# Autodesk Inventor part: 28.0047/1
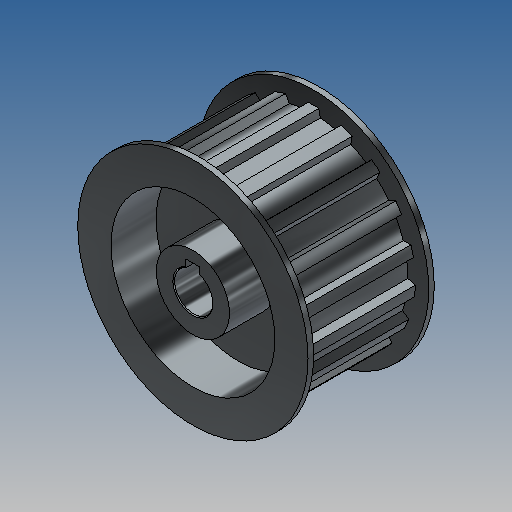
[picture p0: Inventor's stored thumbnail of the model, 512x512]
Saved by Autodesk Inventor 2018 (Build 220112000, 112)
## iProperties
Created: 2006-12
Document SubType Name: Modeling
Designer: Andy Moles
Material: Aluminum-6061
Part Number: 28.0047/1
Density: 2.71 g/cm^3
Description: T45 PULLEY 11mm
Appearance: Zinc
Author: Andy Moles
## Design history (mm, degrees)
sketch "Sketch1"
  geometry: L1 (-1.927, 26.982)-(-1.524, 29.17); L2 (1.927, 26.982)-(1.524, 29.17); L3 (11.073, 27.03)-(10.707, 24.842); L4 (15.084, 22.455)-(16.683, 23.977); L5 (19.077, 22.12)-(18.136, 20.071); L6 (21.534, 16.371)-(23.587, 17.23); L7 (25.254, 14.678)-(23.643, 13.144); L8 (25.717, 8.391)-(27.944, 8.508); L9 (28.652, 5.683)-(26.63, 4.755); L10 (27.049, -0.307)-(29.196, -0.889); L11 (28.945, -3.928)-(26.741, -4.085); L12 (25.484, -9.074)-(27.339, -10.286); L13 (26.084, -13.147)-(23.954, -12.569); L14 (21.157, -16.857)-(22.493, -18.635); L15 (20.429, -20.878)-(18.546, -19.693); L16 (14.537, -22.813)-(15.224, -24.929); L17 (12.543, -26.38)-(11.147, -24.648); L18 (6.342, -26.297)-(6.304, -28.522); L19 (3.298, -29.023)-(2.54, -26.931); L20 (-2.54, -26.931)-(-3.298, -29.023); L21 (-6.304, -28.522)-(-6.342, -26.297); L22 (-11.183, -24.631)-(-12.509, -26.396); L23 (-15.224, -24.929)-(-14.537, -22.813); L24 (-18.546, -19.693)-(-20.429, -20.878); L25 (-22.494, -18.635)-(-21.157, -16.856); L26 (-23.935, -12.604)-(-26.101, -13.113); L27 (-27.325, -10.322)-(-25.484, -9.074); L28 (-26.731, -4.15)-(-28.945, -3.928); L29 (-29.196, -0.89)-(-27.049, -0.307); L30 (-26.63, 4.756)-(-28.652, 5.685); L31 (-27.892, 8.674)-(-25.696, 8.455); L32 (-23.643, 13.144)-(-25.254, 14.679); L33 (-23.587, 17.23)-(-21.534, 16.371); L34 (-18.094, 20.109)-(-19.119, 22.083); L35 (-16.714, 23.955)-(-15.052, 22.477); L36 (-10.707, 24.842)-(-11.073, 27.03); L37 (-8.03, 28.085)-(-6.938, 26.146); L38 (6.938, 26.146)-(7.851, 28.135); A1 r 29.21 centre (0, 0) between (-16.714, 23.955) and (-19.119, 22.083); A2 r 27.051 centre (0, 0) between (-10.707, 24.842) and (-15.052, 22.477); A3 r 29.21 centre (0, 0) between (-8.03, 28.085) and (-11.073, 27.03); A4 r 27.051 centre (0, 0) between (-1.927, 26.982) and (-6.938, 26.146); A5 r 29.21 centre (0, 0) between (1.524, 29.17) and (-1.524, 29.17); A6 r 29.21 centre (0, 0) between (11.073, 27.03) and (7.851, 28.135); A7 r 29.21 centre (0, 0) between (19.077, 22.12) and (16.683, 23.977); A8 r 27.051 centre (0, 0) between (15.084, 22.455) and (10.707, 24.842); A9 r 27.051 centre (0, 0) between (21.534, 16.371) and (18.136, 20.071); A10 r 29.21 centre (0, 0) between (25.254, 14.678) and (23.587, 17.23); A11 r 27.051 centre (0, 0) between (25.717, 8.391) and (23.643, 13.144); A12 r 29.21 centre (0, 0) between (28.652, 5.683) and (27.944, 8.508); A13 r 27.051 centre (0, 0) between (27.049, -0.307) and (26.63, 4.755); A14 r 29.21 centre (0, 0) between (28.945, -3.928) and (29.196, -0.889); A15 r 27.051 centre (0, 0) between (25.484, -9.074) and (26.741, -4.085); A16 r 29.21 centre (0, 0) between (26.084, -13.147) and (27.339, -10.286); A17 r 27.051 centre (0, 0) between (21.157, -16.857) and (23.954, -12.569); A18 r 29.21 centre (0, 0) between (20.429, -20.878) and (22.493, -18.635); A19 r 27.051 centre (0, 0) between (14.537, -22.813) and (18.546, -19.693); A20 r 29.21 centre (0, 0) between (12.543, -26.38) and (15.224, -24.929); A21 r 27.051 centre (0, 0) between (6.342, -26.297) and (11.147, -24.648); A22 r 29.21 centre (0, 0) between (3.298, -29.023) and (6.304, -28.522); A23 r 27.051 centre (0, 0) between (-2.54, -26.931) and (2.54, -26.931); A24 r 29.21 centre (0, 0) between (-6.304, -28.522) and (-3.298, -29.023); A25 r 29.21 centre (0, 0) between (-15.224, -24.929) and (-12.509, -26.396); A26 r 29.21 centre (0, 0) between (-22.494, -18.635) and (-20.429, -20.878); A27 r 27.051 centre (0, 0) between (-11.183, -24.631) and (-6.342, -26.297); A28 r 27.051 centre (0, 0) between (-18.546, -19.693) and (-14.537, -22.813); A29 r 29.21 centre (0, 0) between (-27.325, -10.322) and (-26.101, -13.113); A30 r 27.051 centre (0, 0) between (-23.935, -12.604) and (-21.157, -16.856); A31 r 27.051 centre (0, 0) between (-26.731, -4.15) and (-25.484, -9.074); A32 r 29.21 centre (0, 0) between (-29.196, -0.89) and (-28.945, -3.928); A33 r 27.051 centre (0, 0) between (-26.63, 4.756) and (-27.049, -0.307); A34 r 29.21 centre (0, 0) between (-23.587, 17.23) and (-25.254, 14.679); A35 r 29.21 centre (0, 0) between (-27.892, 8.674) and (-28.652, 5.685); A36 r 27.051 centre (0, 0) between (-18.094, 20.109) and (-21.534, 16.371); A37 r 27.051 centre (0, 0) between (-23.643, 13.144) and (-25.696, 8.455); A38 r 27.051 centre (0, 0) between (6.938, 26.146) and (1.927, 26.982); 2 further points
  constraints: 77 point on circle, 76 end point, 38 centre point, 4 parallel, 2 coincident, 2 perpendicular
extrude "Extrusion1" new body sketch "Sketch1" stored distance "d19" = 33; taper "d20" = 0 deg
sketch "Sketch4"
  geometry: C1 r 33.02 at (0, 0); A1 r 27.051 centre (0, 0) between (6.938, 26.146) and (1.927, 26.982) reference
  constraints: 1 centre point, 1 coincident
  dimensions: "d24" = 66.04 diameter of C1
extrude "Extrusion3" join sketch "Sketch4" distance "d25" = 1.6; taper "d26" = 0 deg
sketch "Sketch5"
  geometry: C1 r 33.02 at (0, 0) reference; C2 r 10.5 at (0, 0); C3 r 23.5 at (0, 0)
  constraints: 2 centre point, 2 coincident
  dimensions: "d27" = 21 diameter of C2; "d28" = 47 diameter of C3
extrude "Extrusion4" cut sketch "Sketch5" distance "d29" = 12.954; taper "d30" = 0 deg
mirror "Mirror1"
sketch "Sketch6"
  geometry: L1 (-2, 5.123)-(-2, 7.3); L2 (-2, 7.3)-(2, 7.3); L3 (2, 7.3)-(2, 5.123); C1 r 10.5 at (0, 0) reference; A1 r 5.5 centre (0, 0) between (-2, 5.123) and (2, 5.123); 1 further point
  constraints: 6 end point, 2 point on circle, 1 centre point, 1 coincident, 1 midpoint, 1 parallel, 1 perpendicular, 1 vertical, 1 vertical alignment
  dimensions: "d31" = 11 diameter of A1 (= SHAFT_DIA); "d34" = 4 distance of L1.end L2.end (= SQUARE_KEY_SIZE); "d35" = 12.8 dimension on A1 L2 (= SHAFT_DIA + t2_KEYWAY_DEPTH)
extrude "Extrusion5" cut sketch "Sketch6" extent not by distance; stored distance "d32" = 12.954; taper "d33" = 0 deg
chamfer "Chamfer1" distance "d36" = 0.25; stored, may be unused: second distance "d37" = 2, angle "d38" = 45 deg
body "Solid1"
other parameters: "d1" = 2.159, "SHAFT_DIA" = 11 [user parameter; used in 2 equation terms], "SQUARE_KEY_SIZE" = 4 [user parameter; used in 1 equation term], "t2_KEYWAY_DEPTH" = 1.8 [user parameter; used in 1 equation term]
